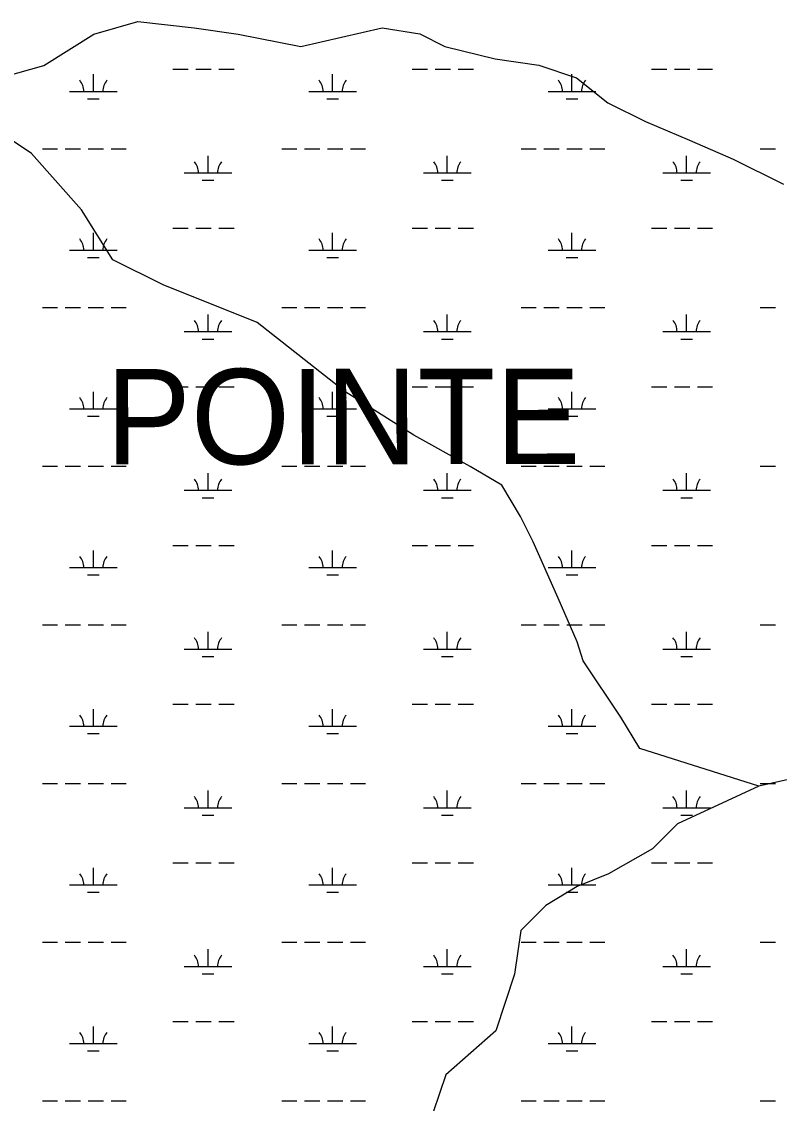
# Model space of a CAD drawing. Extents: x 3192927 to 3230760, y 831141 to 856475.
# Drawn here: x 3209720 to 3211309, y 843112 to 845380 of the extents above; entities that cross this region are included whole.
import ezdxf

# ---------------------------------------------------------------- set-up
doc = ezdxf.new("R2010")
doc.units = 0
for name, color, linetype in [('V-TOPO-GNAM-IDEN', 7, 'Continuous'), ('V-TOPO-SHOR', 7, 'Continuous'), ('V-WETL-SWMP', 7, 'Continuous')]:
    doc.layers.add(name, color=color, linetype=linetype)

msp = doc.modelspace()

# ---------------------------------------------------------------- linework, layer by layer
at = {"layer": 'V-TOPO-SHOR'}
for points in [[(3209530.1, 845221.9), (3209766.7, 845287.8), (3209871.8, 845353.6), (3209963.8, 845379.9), (3210082.1, 845366.9), (3210174.1, 845353.8), (3210305.5, 845327.6), (3210476.4, 845367.2), (3210555.2, 845354.1), (3210607.8, 845327.9), (3210713, 845301.7), (3210805, 845288.6), (3210883.9, 845262.4), (3210949.7, 845209.9), (3211028.6, 845170.5), (3211120.6, 845131.2), (3211212.6, 845091.8), (3211317.8, 845039.3)], [(3211384.6, 843803.9), (3211266.3, 843777.5), (3211016.5, 843856.1), (3210977, 843921.8), (3210898.1, 844040.1), (3210884.9, 844079.5), (3210845.4, 844171.4), (3210792.7, 844289.7), (3210766.4, 844342.2), (3210726.9, 844407.9), (3210661.1, 844447.3), (3210661.1, 844447.3), (3210542.8, 844512.9), (3210398.1, 844604.8), (3210214, 844749.2), (3210016.8, 844827.9), (3209911.6, 844880.4), (3209845.8, 844985.5), (3209740.5, 845103.7), (3209661.6, 845156.2)], [(3211266.3, 843777.5), (3211095.5, 843698.5), (3211043, 843645.9), (3210951, 843593.2), (3210885.3, 843566.9), (3210819.6, 843527.4), (3210767.1, 843474.8), (3210754, 843382.8), (3210714.7, 843264.4), (3210609.6, 843172.3), (3210583.4, 843093.5)]]:
    msp.add_lwpolyline(points, dxfattribs=at)
at = {"layer": 'V-WETL-SWMP'}
for p, q in [((3209870.5, 845233.6), (3209870.5, 845269.6)), ((3210037.5, 845280), (3210069.5, 845280)), ((3210085.5, 845280), (3210117.5, 845280)), ((3210133.5, 845280), (3210165.5, 845280)), ((3210372.4, 845233.6), (3210372.4, 845269.6)), ((3210539.5, 845280), (3210571.5, 845280)), ((3210587.5, 845280), (3210619.5, 845280)), ((3210635.5, 845280), (3210667.5, 845280)), ((3210874.3, 845233.6), (3210874.3, 845269.6)), ((3211041.4, 845280), (3211073.4, 845280)), ((3211089.4, 845280), (3211121.4, 845280)), ((3211137.4, 845280), (3211169.4, 845280)), ((3209820.5, 845233.6), (3209920.5, 845233.6)), ((3210322.4, 845233.6), (3210422.4, 845233.6)), ((3210824.3, 845233.6), (3210924.3, 845233.6)), ((3209858.5, 845218.1), (3209882.5, 845218.1)), ((3210360.4, 845218.1), (3210384.4, 845218.1)), ((3210862.3, 845218.1), (3210886.3, 845218.1)), ((3209763.6, 845113.5), (3209795.6, 845113.5)), ((3209811.6, 845113.5), (3209843.6, 845113.5)), ((3209859.6, 845113.5), (3209891.6, 845113.5)), ((3209907.6, 845113.5), (3209939.6, 845113.5)), ((3210265.5, 845113.5), (3210297.5, 845113.5)), ((3210313.5, 845113.5), (3210345.5, 845113.5)), ((3210361.5, 845113.5), (3210393.5, 845113.5)), ((3210409.5, 845113.5), (3210441.5, 845113.5)), ((3210767.5, 845113.5), (3210799.5, 845113.5)), ((3210815.5, 845113.5), (3210847.5, 845113.5)), ((3210863.5, 845113.5), (3210895.5, 845113.5)), ((3210911.5, 845113.5), (3210943.5, 845113.5)), ((3211269.4, 845113.5), (3211301.4, 845113.5)), ((3210111, 845062.8), (3210111, 845098.8)), ((3210612.9, 845062.8), (3210612.9, 845098.8)), ((3211114.8, 845062.8), (3211114.8, 845098.8)), ((3210061, 845062.8), (3210161, 845062.8)), ((3210099, 845047.3), (3210123, 845047.3)), ((3210562.9, 845062.8), (3210662.9, 845062.8)), ((3210600.9, 845047.3), (3210624.9, 845047.3)), ((3211064.8, 845062.8), (3211164.8, 845062.8)), ((3211102.8, 845047.3), (3211126.8, 845047.3)), ((3209870.5, 844900.9), (3209870.5, 844936.9)), ((3210037.5, 844947.3), (3210069.5, 844947.3)), ((3210085.5, 844947.3), (3210117.5, 844947.3)), ((3210133.5, 844947.3), (3210165.5, 844947.3)), ((3210372.4, 844900.9), (3210372.4, 844936.9)), ((3210539.5, 844947.3), (3210571.5, 844947.3)), ((3210587.5, 844947.3), (3210619.5, 844947.3)), ((3210635.5, 844947.3), (3210667.5, 844947.3)), ((3210874.3, 844900.9), (3210874.3, 844936.9)), ((3211041.4, 844947.3), (3211073.4, 844947.3)), ((3211089.4, 844947.3), (3211121.4, 844947.3)), ((3211137.4, 844947.3), (3211169.4, 844947.3)), ((3209820.5, 844900.9), (3209920.5, 844900.9)), ((3209858.5, 844885.5), (3209882.5, 844885.5)), ((3210322.4, 844900.9), (3210422.4, 844900.9)), ((3210360.4, 844885.5), (3210384.4, 844885.5)), ((3210824.3, 844900.9), (3210924.3, 844900.9)), ((3210862.3, 844885.5), (3210886.3, 844885.5)), ((3209763.6, 844780.8), (3209795.6, 844780.8)), ((3209811.6, 844780.8), (3209843.6, 844780.8)), ((3209859.6, 844780.8), (3209891.6, 844780.8)), ((3209907.6, 844780.8), (3209939.6, 844780.8)), ((3210265.5, 844780.8), (3210297.5, 844780.8)), ((3210313.5, 844780.8), (3210345.5, 844780.8)), ((3210361.5, 844780.8), (3210393.5, 844780.8)), ((3210409.5, 844780.8), (3210441.5, 844780.8)), ((3210767.5, 844780.8), (3210799.5, 844780.8)), ((3210815.5, 844780.8), (3210847.5, 844780.8)), ((3210863.5, 844780.8), (3210895.5, 844780.8)), ((3210911.5, 844780.8), (3210943.5, 844780.8)), ((3211269.4, 844780.8), (3211301.4, 844780.8)), ((3210111, 844730.1), (3210111, 844766.1)), ((3210612.9, 844730.1), (3210612.9, 844766.1)), ((3211114.8, 844730.1), (3211114.8, 844766.1)), ((3210061, 844730.1), (3210161, 844730.1)), ((3210562.9, 844730.1), (3210662.9, 844730.1)), ((3211064.8, 844730.1), (3211164.8, 844730.1)), ((3210099, 844714.6), (3210123, 844714.6)), ((3210600.9, 844714.6), (3210624.9, 844714.6)), ((3211102.8, 844714.6), (3211126.8, 844714.6)), ((3210037.5, 844614.6), (3210069.5, 844614.6)), ((3210085.5, 844614.6), (3210117.5, 844614.6)), ((3210133.5, 844614.6), (3210165.5, 844614.6)), ((3210539.5, 844614.6), (3210571.5, 844614.6)), ((3210587.5, 844614.6), (3210619.5, 844614.6)), ((3210635.5, 844614.6), (3210667.5, 844614.6)), ((3211041.4, 844614.6), (3211073.4, 844614.6)), ((3211089.4, 844614.6), (3211121.4, 844614.6)), ((3211137.4, 844614.6), (3211169.4, 844614.6)), ((3209870.5, 844568.2), (3209870.5, 844604.2)), ((3210372.4, 844568.2), (3210372.4, 844604.2)), ((3210874.3, 844568.2), (3210874.3, 844604.2)), ((3209820.5, 844568.2), (3209920.5, 844568.2)), ((3210322.4, 844568.2), (3210422.4, 844568.2)), ((3210824.3, 844568.2), (3210924.3, 844568.2)), ((3209858.5, 844552.8), (3209882.5, 844552.8)), ((3210360.4, 844552.8), (3210384.4, 844552.8)), ((3210862.3, 844552.8), (3210886.3, 844552.8)), ((3209763.6, 844448.1), (3209795.6, 844448.1)), ((3209811.6, 844448.1), (3209843.6, 844448.1)), ((3209859.6, 844448.1), (3209891.6, 844448.1)), ((3209907.6, 844448.1), (3209939.6, 844448.1)), ((3210111, 844397.4), (3210111, 844433.4)), ((3210265.5, 844448.1), (3210297.5, 844448.1)), ((3210313.5, 844448.1), (3210345.5, 844448.1)), ((3210361.5, 844448.1), (3210393.5, 844448.1)), ((3210409.5, 844448.1), (3210441.5, 844448.1)), ((3210612.9, 844397.4), (3210612.9, 844433.4)), ((3210767.5, 844448.1), (3210799.5, 844448.1)), ((3210815.5, 844448.1), (3210847.5, 844448.1)), ((3210863.5, 844448.1), (3210895.5, 844448.1)), ((3210911.5, 844448.1), (3210943.5, 844448.1)), ((3211114.8, 844397.4), (3211114.8, 844433.4)), ((3211269.4, 844448.1), (3211301.4, 844448.1)), ((3210061, 844397.4), (3210161, 844397.4)), ((3210562.9, 844397.4), (3210662.9, 844397.4)), ((3211064.8, 844397.4), (3211164.8, 844397.4)), ((3210099, 844382), (3210123, 844382)), ((3210600.9, 844382), (3210624.9, 844382)), ((3211102.8, 844382), (3211126.8, 844382)), ((3210037.5, 844282), (3210069.5, 844282)), ((3210085.5, 844282), (3210117.5, 844282)), ((3210133.5, 844282), (3210165.5, 844282)), ((3210539.5, 844282), (3210571.5, 844282)), ((3210587.5, 844282), (3210619.5, 844282)), ((3210635.5, 844282), (3210667.5, 844282)), ((3211041.4, 844282), (3211073.4, 844282)), ((3211089.4, 844282), (3211121.4, 844282)), ((3211137.4, 844282), (3211169.4, 844282)), ((3209870.5, 844235.5), (3209870.5, 844271.5)), ((3210372.4, 844235.5), (3210372.4, 844271.5)), ((3210874.3, 844235.5), (3210874.3, 844271.5)), ((3209820.5, 844235.5), (3209920.5, 844235.5)), ((3210322.4, 844235.5), (3210422.4, 844235.5)), ((3210824.3, 844235.5), (3210924.3, 844235.5)), ((3209858.5, 844220.1), (3209882.5, 844220.1)), ((3210360.4, 844220.1), (3210384.4, 844220.1)), ((3210862.3, 844220.1), (3210886.3, 844220.1)), ((3209763.6, 844115.5), (3209795.6, 844115.5)), ((3209811.6, 844115.5), (3209843.6, 844115.5)), ((3209859.6, 844115.5), (3209891.6, 844115.5)), ((3209907.6, 844115.5), (3209939.6, 844115.5)), ((3210265.5, 844115.5), (3210297.5, 844115.5)), ((3210313.5, 844115.5), (3210345.5, 844115.5)), ((3210361.5, 844115.5), (3210393.5, 844115.5)), ((3210409.5, 844115.5), (3210441.5, 844115.5)), ((3210767.5, 844115.5), (3210799.5, 844115.5)), ((3210815.5, 844115.5), (3210847.5, 844115.5)), ((3210863.5, 844115.5), (3210895.5, 844115.5)), ((3210911.5, 844115.5), (3210943.5, 844115.5)), ((3211269.4, 844115.5), (3211301.4, 844115.5)), ((3210111, 844064.7), (3210111, 844100.7)), ((3210612.9, 844064.7), (3210612.9, 844100.7)), ((3211114.8, 844064.7), (3211114.8, 844100.7)), ((3210061, 844064.7), (3210161, 844064.7)), ((3210099, 844049.3), (3210123, 844049.3)), ((3210562.9, 844064.7), (3210662.9, 844064.7)), ((3210600.9, 844049.3), (3210624.9, 844049.3)), ((3211064.8, 844064.7), (3211164.8, 844064.7)), ((3211102.8, 844049.3), (3211126.8, 844049.3)), ((3209870.5, 843902.9), (3209870.5, 843938.9)), ((3210037.5, 843949.3), (3210069.5, 843949.3)), ((3210085.5, 843949.3), (3210117.5, 843949.3)), ((3210133.5, 843949.3), (3210165.5, 843949.3)), ((3210372.4, 843902.9), (3210372.4, 843938.9)), ((3210539.5, 843949.3), (3210571.5, 843949.3)), ((3210587.5, 843949.3), (3210619.5, 843949.3)), ((3210635.5, 843949.3), (3210667.5, 843949.3)), ((3210874.3, 843902.9), (3210874.3, 843938.9)), ((3211041.4, 843949.3), (3211073.4, 843949.3)), ((3211089.4, 843949.3), (3211121.4, 843949.3)), ((3211137.4, 843949.3), (3211169.4, 843949.3)), ((3209820.5, 843902.9), (3209920.5, 843902.9)), ((3209858.5, 843887.4), (3209882.5, 843887.4)), ((3210322.4, 843902.9), (3210422.4, 843902.9)), ((3210360.4, 843887.4), (3210384.4, 843887.4)), ((3210824.3, 843902.9), (3210924.3, 843902.9)), ((3210862.3, 843887.4), (3210886.3, 843887.4)), ((3209763.6, 843782.8), (3209795.6, 843782.8)), ((3209811.6, 843782.8), (3209843.6, 843782.8)), ((3209859.6, 843782.8), (3209891.6, 843782.8)), ((3209907.6, 843782.8), (3209939.6, 843782.8)), ((3210265.5, 843782.8), (3210297.5, 843782.8)), ((3210313.5, 843782.8), (3210345.5, 843782.8)), ((3210361.5, 843782.8), (3210393.5, 843782.8)), ((3210409.5, 843782.8), (3210441.5, 843782.8)), ((3210767.5, 843782.8), (3210799.5, 843782.8)), ((3210815.5, 843782.8), (3210847.5, 843782.8)), ((3210863.5, 843782.8), (3210895.5, 843782.8)), ((3210911.5, 843782.8), (3210943.5, 843782.8)), ((3211269.4, 843782.8), (3211301.4, 843782.8)), ((3210111, 843732.1), (3210111, 843768.1)), ((3210612.9, 843732.1), (3210612.9, 843768.1)), ((3211114.8, 843732.1), (3211114.8, 843768.1)), ((3210061, 843732.1), (3210161, 843732.1)), ((3210562.9, 843732.1), (3210662.9, 843732.1)), ((3211064.8, 843732.1), (3211164.8, 843732.1)), ((3210099, 843716.6), (3210123, 843716.6)), ((3210600.9, 843716.6), (3210624.9, 843716.6)), ((3211102.8, 843716.6), (3211126.8, 843716.6)), ((3210037.5, 843616.6), (3210069.5, 843616.6)), ((3210085.5, 843616.6), (3210117.5, 843616.6)), ((3210133.5, 843616.6), (3210165.5, 843616.6)), ((3210539.5, 843616.6), (3210571.5, 843616.6)), ((3210587.5, 843616.6), (3210619.5, 843616.6)), ((3210635.5, 843616.6), (3210667.5, 843616.6)), ((3211041.4, 843616.6), (3211073.4, 843616.6)), ((3211089.4, 843616.6), (3211121.4, 843616.6)), ((3211137.4, 843616.6), (3211169.4, 843616.6)), ((3209870.5, 843570.2), (3209870.5, 843606.2)), ((3210372.4, 843570.2), (3210372.4, 843606.2)), ((3210874.3, 843570.2), (3210874.3, 843606.2)), ((3209820.5, 843570.2), (3209920.5, 843570.2)), ((3210322.4, 843570.2), (3210422.4, 843570.2)), ((3210824.3, 843570.2), (3210924.3, 843570.2)), ((3209858.5, 843554.8), (3209882.5, 843554.8)), ((3210360.4, 843554.8), (3210384.4, 843554.8)), ((3210862.3, 843554.8), (3210886.3, 843554.8)), ((3209763.6, 843450.1), (3209795.6, 843450.1)), ((3209811.6, 843450.1), (3209843.6, 843450.1)), ((3209859.6, 843450.1), (3209891.6, 843450.1)), ((3209907.6, 843450.1), (3209939.6, 843450.1)), ((3210111, 843399.4), (3210111, 843435.4)), ((3210265.5, 843450.1), (3210297.5, 843450.1)), ((3210313.5, 843450.1), (3210345.5, 843450.1)), ((3210361.5, 843450.1), (3210393.5, 843450.1)), ((3210409.5, 843450.1), (3210441.5, 843450.1)), ((3210612.9, 843399.4), (3210612.9, 843435.4)), ((3210767.5, 843450.1), (3210799.5, 843450.1)), ((3210815.5, 843450.1), (3210847.5, 843450.1)), ((3210863.5, 843450.1), (3210895.5, 843450.1)), ((3210911.5, 843450.1), (3210943.5, 843450.1)), ((3211114.8, 843399.4), (3211114.8, 843435.4)), ((3211269.4, 843450.1), (3211301.4, 843450.1)), ((3210061, 843399.4), (3210161, 843399.4)), ((3210562.9, 843399.4), (3210662.9, 843399.4)), ((3211064.8, 843399.4), (3211164.8, 843399.4)), ((3210099, 843383.9), (3210123, 843383.9)), ((3210600.9, 843383.9), (3210624.9, 843383.9)), ((3211102.8, 843383.9), (3211126.8, 843383.9)), ((3210037.5, 843283.9), (3210069.5, 843283.9)), ((3210085.5, 843283.9), (3210117.5, 843283.9)), ((3210133.5, 843283.9), (3210165.5, 843283.9)), ((3210539.5, 843283.9), (3210571.5, 843283.9)), ((3210587.5, 843283.9), (3210619.5, 843283.9)), ((3210635.5, 843283.9), (3210667.5, 843283.9)), ((3211041.4, 843283.9), (3211073.4, 843283.9)), ((3211089.4, 843283.9), (3211121.4, 843283.9)), ((3211137.4, 843283.9), (3211169.4, 843283.9)), ((3209870.5, 843237.5), (3209870.5, 843273.5)), ((3210372.4, 843237.5), (3210372.4, 843273.5)), ((3210874.3, 843237.5), (3210874.3, 843273.5)), ((3209820.5, 843237.5), (3209920.5, 843237.5)), ((3210322.4, 843237.5), (3210422.4, 843237.5)), ((3210824.3, 843237.5), (3210924.3, 843237.5)), ((3209858.5, 843222.1), (3209882.5, 843222.1)), ((3210360.4, 843222.1), (3210384.4, 843222.1)), ((3210862.3, 843222.1), (3210886.3, 843222.1)), ((3209763.6, 843117.4), (3209795.6, 843117.4)), ((3209811.6, 843117.4), (3209843.6, 843117.4)), ((3209859.6, 843117.4), (3209891.6, 843117.4)), ((3209907.6, 843117.4), (3209939.6, 843117.4)), ((3210265.5, 843117.4), (3210297.5, 843117.4)), ((3210313.5, 843117.4), (3210345.5, 843117.4)), ((3210361.5, 843117.4), (3210393.5, 843117.4)), ((3210409.5, 843117.4), (3210441.5, 843117.4)), ((3210767.5, 843117.4), (3210799.5, 843117.4)), ((3210815.5, 843117.4), (3210847.5, 843117.4)), ((3210863.5, 843117.4), (3210895.5, 843117.4)), ((3210911.5, 843117.4), (3210943.5, 843117.4)), ((3211269.4, 843117.4), (3211301.4, 843117.4))]:
    msp.add_line(p, q, dxfattribs=at)
for centre, start, end in [((3209815.2, 845234), 359.2282, 40.7718), ((3209925.7, 845234), 139.2282, 180.7718), ((3210317.1, 845234), 359.2282, 40.7718), ((3210427.6, 845234), 139.2282, 180.7718), ((3210819.1, 845234), 359.2282, 40.7718), ((3210929.5, 845234), 139.2282, 180.7718), ((3210055.7, 845063.2), 359.2282, 40.7718), ((3210166.2, 845063.2), 139.2282, 180.7718), ((3210557.6, 845063.2), 359.2282, 40.7718), ((3210668.1, 845063.2), 139.2282, 180.7718), ((3211059.5, 845063.2), 359.2282, 40.7718), ((3211170, 845063.2), 139.2282, 180.7718), ((3209815.2, 844901.4), 359.2282, 40.7718), ((3209925.7, 844901.4), 139.2282, 180.7718), ((3210317.1, 844901.4), 359.2282, 40.7718), ((3210427.6, 844901.4), 139.2282, 180.7718), ((3210819.1, 844901.4), 359.2282, 40.7718), ((3210929.5, 844901.4), 139.2282, 180.7718), ((3210055.7, 844730.6), 359.2282, 40.7718), ((3210166.2, 844730.6), 139.2282, 180.7718), ((3210557.6, 844730.6), 359.2282, 40.7718), ((3210668.1, 844730.6), 139.2282, 180.7718), ((3211059.5, 844730.6), 359.2282, 40.7718), ((3211170, 844730.6), 139.2282, 180.7718), ((3209815.2, 844568.7), 359.2282, 40.7718), ((3209925.7, 844568.7), 139.2282, 180.7718), ((3210317.1, 844568.7), 359.2282, 40.7718), ((3210427.6, 844568.7), 139.2282, 180.7718), ((3210819.1, 844568.7), 359.2282, 40.7718), ((3210929.5, 844568.7), 139.2282, 180.7718), ((3210055.7, 844397.9), 359.2282, 40.7718), ((3210166.2, 844397.9), 139.2282, 180.7718), ((3210557.6, 844397.9), 359.2282, 40.7718), ((3210668.1, 844397.9), 139.2282, 180.7718), ((3211059.5, 844397.9), 359.2282, 40.7718), ((3211170, 844397.9), 139.2282, 180.7718), ((3209815.2, 844236), 359.2282, 40.7718), ((3209925.7, 844236), 139.2282, 180.7718), ((3210317.1, 844236), 359.2282, 40.7718), ((3210427.6, 844236), 139.2282, 180.7718), ((3210819.1, 844236), 359.2282, 40.7718), ((3210929.5, 844236), 139.2282, 180.7718), ((3210055.7, 844065.2), 359.2282, 40.7718), ((3210166.2, 844065.2), 139.2282, 180.7718), ((3210557.6, 844065.2), 359.2282, 40.7718), ((3210668.1, 844065.2), 139.2282, 180.7718), ((3211059.5, 844065.2), 359.2282, 40.7718), ((3211170, 844065.2), 139.2282, 180.7718), ((3209815.2, 843903.3), 359.2282, 40.7718), ((3209925.7, 843903.3), 139.2282, 180.7718), ((3210317.1, 843903.3), 359.2282, 40.7718), ((3210427.6, 843903.3), 139.2282, 180.7718), ((3210819.1, 843903.3), 359.2282, 40.7718), ((3210929.5, 843903.3), 139.2282, 180.7718), ((3210055.7, 843732.5), 359.2282, 40.7718), ((3210166.2, 843732.5), 139.2282, 180.7718), ((3210557.6, 843732.5), 359.2282, 40.7718), ((3210668.1, 843732.5), 139.2282, 180.7718), ((3211059.5, 843732.5), 359.2282, 40.7718), ((3211170, 843732.5), 139.2282, 180.7718), ((3209815.2, 843570.7), 359.2282, 40.7718), ((3209925.7, 843570.7), 139.2282, 180.7718), ((3210317.1, 843570.7), 359.2282, 40.7718), ((3210427.6, 843570.7), 139.2282, 180.7718), ((3210819.1, 843570.7), 359.2282, 40.7718), ((3210929.5, 843570.7), 139.2282, 180.7718), ((3210055.7, 843399.9), 359.2282, 40.7718), ((3210166.2, 843399.9), 139.2282, 180.7718), ((3210557.6, 843399.9), 359.2282, 40.7718), ((3210668.1, 843399.9), 139.2282, 180.7718), ((3211059.5, 843399.9), 359.2282, 40.7718), ((3211170, 843399.9), 139.2282, 180.7718), ((3209815.2, 843238), 359.2282, 40.7718), ((3209925.7, 843238), 139.2282, 180.7718), ((3210317.1, 843238), 359.2282, 40.7718), ((3210427.6, 843238), 139.2282, 180.7718), ((3210819.1, 843238), 359.2282, 40.7718), ((3210929.5, 843238), 139.2282, 180.7718)]:
    msp.add_arc(centre, 35.2, start, end, dxfattribs=at)

# ---------------------------------------------------------------- texts
at = {"layer": 'V-TOPO-GNAM-IDEN'}
msp.add_text('POINTE', height=200, rotation=0.047, dxfattribs=at).set_placement((3209896.7, 844451.7))

doc.saveas('drawing.dxf')
